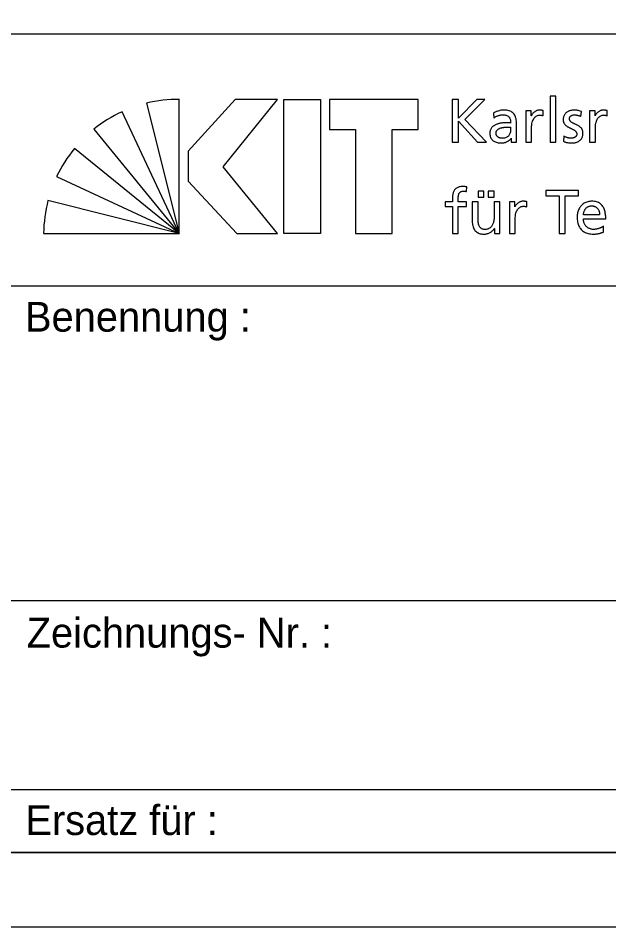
# Model space of a CAD drawing. Extents: x 0 to 29.7, y 0 to 21.
# Drawn here: x 25.283 to 27.266, y 0 to 3.052 of the extents above; entities that cross this region are included whole.
import ezdxf

# ---------------------------------------------------------------- set-up
doc = ezdxf.new("R2010")
doc.units = 0
doc.layers.add('90_Plankopf', color=7, linetype='Continuous')

msp = doc.modelspace()

# ---------------------------------------------------------------- linework, layer by layer
at = {"layer": '90_Plankopf'}
for p, q in [((20.556, 2.9995), (29.45, 2.9995)), ((20.556, 2.9995), (29.45, 2.9995)), ((25.824, 2.3293), (25.824, 2.7792)), ((26.7405, 2.7793), (26.7405, 2.6353)), ((25.7137, 2.7666), (25.824, 2.3293)), ((25.824, 2.3293), (25.6317, 2.7376)), ((26.879, 2.7331), (26.88, 2.7166)), ((27.0463, 2.7242), (27.0463, 2.7416)), ((27.1728, 2.722), (27.1745, 2.7389)), ((27.2606, 2.7242), (27.2606, 2.7416)), ((26.9559, 2.6559), (26.9559, 2.6995)), ((25.5372, 2.6793), (25.824, 2.3293)), ((26.9365, 2.6854), (26.9365, 2.6761)), ((27.1149, 2.6559), (27.1138, 2.6386)), ((26.7405, 2.6353), (26.7611, 2.6353)), ((26.8253, 2.6353), (26.8554, 2.6353)), ((25.824, 2.3293), (25.4717, 2.6143)), ((25.412, 2.5207), (25.824, 2.3293)), ((26.7887, 2.4696), (26.7895, 2.4853)), ((25.824, 2.3293), (25.3829, 2.4394)), ((26.9913, 2.4182), (26.9913, 2.4356)), ((27.2353, 2.392), (27.1808, 2.392)), ((27.1808, 2.3776), (27.2559, 2.3776)), ((27.2479, 2.3337), (27.2479, 2.353)), ((25.3682, 2.3293), (25.824, 2.3293)), ((25.2501, 2.1535), (29.45, 2.1535)), ((25.2501, 1.096), (29.45, 1.096)), ((25.2501, 0.4615), (29.45, 0.4615)), ((29.45, 0.25), (20.556, 0.25)), ((21.14, 0.25), (29.45, 0.25)), ((21.14, 0.25), (29.45, 0.25))]:
    msp.add_line(p, q, dxfattribs=at)
for points in [[(0, 0), (29.7, 0), (29.7, 21), (0, 21)], [(1.25, 20.75), (29.45, 20.75), (29.45, 0.25), (1.25, 0.25)], [(26.1533, 2.7793), (26.0118, 2.7793), (25.8536, 2.6049), (25.8536, 2.5046), (26.0169, 2.3293), (26.1542, 2.3293), (25.9711, 2.5531)], [(26.2985, 2.7793), (26.2985, 2.3293), (26.1751, 2.3293), (26.1751, 2.7793)], [(26.3281, 2.7793), (26.3281, 2.678), (26.4151, 2.678), (26.4151, 2.3293), (26.5385, 2.3293), (26.5385, 2.678), (26.6255, 2.678), (26.6255, 2.7793)]]:
    msp.add_lwpolyline(points, close=True, dxfattribs=at)
for points in [[(26.8554, 2.6353), (26.7824, 2.7112), (26.85, 2.7793), (26.8226, 2.7793), (26.7611, 2.716), (26.7611, 2.7793), (26.7405, 2.7793)], [(27.069, 2.6353), (27.0884, 2.6353), (27.0884, 2.79), (27.069, 2.79), (27.069, 2.6353)], [(27.0061, 2.7242), (27.0057, 2.7242), (27.0057, 2.7405), (26.9875, 2.7405), (26.9875, 2.6353), (27.0069, 2.6353), (27.0069, 2.6832)], [(27.2203, 2.7242), (27.2199, 2.7242), (27.2199, 2.7405), (27.2018, 2.7405), (27.2018, 2.6353), (27.2212, 2.6353), (27.2212, 2.6832)], [(26.7611, 2.6353), (26.7611, 2.7059), (26.8253, 2.6353)], [(26.9382, 2.6489), (26.9386, 2.6489), (26.9386, 2.6353), (26.9567, 2.6353)], [(27.0995, 2.3293), (27.1201, 2.3293), (27.1201, 2.4552), (27.1649, 2.4552), (27.1649, 2.4733), (27.0547, 2.4733), (27.0547, 2.4552), (27.0995, 2.4552), (27.0995, 2.3293)], [(26.7412, 2.4443), (26.7412, 2.4346), (26.7165, 2.4346), (26.7165, 2.4189), (26.7412, 2.4189), (26.7412, 2.3293), (26.7606, 2.3293), (26.7606, 2.4189), (26.7885, 2.4189), (26.7885, 2.4346), (26.7606, 2.4346), (26.7606, 2.4459)], [(26.8277, 2.4713), (26.8277, 2.4506), (26.8471, 2.4506), (26.8471, 2.4713), (26.8277, 2.4713)], [(26.8615, 2.4713), (26.8615, 2.4506), (26.8809, 2.4506), (26.8809, 2.4713), (26.8615, 2.4713)], [(26.8271, 2.3801), (26.8271, 2.4346), (26.8077, 2.4346), (26.8077, 2.372)], [(26.9007, 2.3293), (26.9007, 2.4346), (26.8813, 2.4346), (26.8813, 2.3859)], [(26.9511, 2.4182), (26.9507, 2.4182), (26.9507, 2.4346), (26.9325, 2.4346), (26.9325, 2.3293), (26.9519, 2.3293), (26.9519, 2.3772)], [(26.8816, 2.346), (26.882, 2.346), (26.882, 2.3293), (26.9007, 2.3293)]]:
    msp.add_lwpolyline(points, dxfattribs=at)
for centre, start, end in [((25.8224, 2.3028), 89.8053, 103.1895), ((25.8331, 2.3059), 115.0126, 128.3968), ((25.8408, 2.3131), 140.7898, 154.174), ((25.8446, 2.3219), 165.7222, 179.1064)]:
    msp.add_arc(centre, 0.4764, start, end, dxfattribs=at)
for points in [[(26.9559, 2.6995), (26.956, 2.709), (26.9545, 2.717), (26.9517, 2.7235), (26.9488, 2.73), (26.9442, 2.7348), (26.938, 2.7381), (26.9317, 2.7413), (26.9236, 2.743), (26.9136, 2.743), (26.9069, 2.743), (26.9007, 2.742), (26.8949, 2.7402), (26.8891, 2.7384), (26.8838, 2.7361), (26.879, 2.7331)], [(26.88, 2.7166), (26.8826, 2.7188), (26.8856, 2.7207), (26.889, 2.7223), (26.8923, 2.7239), (26.8958, 2.7251), (26.8995, 2.726), (26.9032, 2.7269), (26.9068, 2.7273), (26.9105, 2.7273), (26.917, 2.7273), (26.9221, 2.7263), (26.9259, 2.7243), (26.9297, 2.7222), (26.9324, 2.7191), (26.9341, 2.7151), (26.9358, 2.711), (26.9365, 2.7059), (26.9365, 2.6999)], [(27.0463, 2.7416), (27.045, 2.7418), (27.0437, 2.7421), (27.0425, 2.7423), (27.0412, 2.7425), (27.0399, 2.7427), (27.0385, 2.7428), (27.0371, 2.7429), (27.0354, 2.743), (27.0335, 2.743), (27.0298, 2.743), (27.0261, 2.7422), (27.0226, 2.7406), (27.0191, 2.739), (27.0159, 2.7368), (27.013, 2.7339), (27.0101, 2.7311), (27.0078, 2.7279), (27.0061, 2.7242)], [(27.0069, 2.6832), (27.0069, 2.692), (27.0081, 2.6996), (27.0105, 2.706), (27.0129, 2.7124), (27.0162, 2.7174), (27.0205, 2.7208), (27.0247, 2.7243), (27.0298, 2.726), (27.0356, 2.7261), (27.0373, 2.7261), (27.039, 2.726), (27.0409, 2.7257), (27.0427, 2.7254), (27.0445, 2.7249), (27.0463, 2.7242)], [(27.1745, 2.7389), (27.1707, 2.74), (27.1669, 2.741), (27.163, 2.7418), (27.1591, 2.7426), (27.1549, 2.743), (27.1504, 2.743), (27.1451, 2.743), (27.1403, 2.7423), (27.1358, 2.741), (27.1313, 2.7397), (27.1274, 2.7377), (27.124, 2.735), (27.1206, 2.7323), (27.118, 2.729), (27.1161, 2.7249), (27.1142, 2.7208), (27.1132, 2.7161), (27.1132, 2.7106), (27.1132, 2.7064), (27.1141, 2.7028), (27.1158, 2.6997), (27.1174, 2.6966), (27.1195, 2.694), (27.1223, 2.6917), (27.125, 2.6895), (27.1279, 2.6875), (27.1312, 2.6857), (27.1344, 2.684), (27.1376, 2.6824), (27.1409, 2.6809), (27.1441, 2.6793), (27.1471, 2.6777), (27.1498, 2.6761), (27.1525, 2.6745), (27.1547, 2.6727), (27.1563, 2.6706), (27.1579, 2.6686), (27.1588, 2.6663), (27.1588, 2.6636), (27.1588, 2.6607), (27.1582, 2.6584), (27.157, 2.6564), (27.1558, 2.6545), (27.1542, 2.6529), (27.1522, 2.6518), (27.1503, 2.6506), (27.1482, 2.6498), (27.1459, 2.6493), (27.1435, 2.6487), (27.1412, 2.6485), (27.139, 2.6485), (27.1371, 2.6485), (27.1347, 2.6488), (27.132, 2.6493), (27.1292, 2.6499), (27.1263, 2.6507), (27.1233, 2.6518), (27.1203, 2.6529), (27.1175, 2.6543), (27.1149, 2.6559)], [(27.1138, 2.6386), (27.1183, 2.6363), (27.123, 2.6347), (27.1279, 2.6339), (27.1328, 2.6331), (27.1377, 2.6327), (27.1427, 2.6328), (27.1475, 2.6328), (27.152, 2.6335), (27.1564, 2.6348), (27.1607, 2.6361), (27.1647, 2.6381), (27.1681, 2.6408), (27.1716, 2.6435), (27.1743, 2.6469), (27.1764, 2.651), (27.1784, 2.6551), (27.1794, 2.66), (27.1795, 2.6656), (27.1794, 2.6704), (27.1786, 2.6745), (27.1769, 2.6778), (27.1753, 2.6811), (27.1731, 2.684), (27.1704, 2.6863), (27.1677, 2.6886), (27.1647, 2.6906), (27.1615, 2.6922), (27.1583, 2.6939), (27.155, 2.6954), (27.1518, 2.6968), (27.1486, 2.6983), (27.1456, 2.6998), (27.1429, 2.7013), (27.1402, 2.7029), (27.138, 2.7047), (27.1364, 2.7068), (27.1347, 2.7089), (27.1339, 2.7115), (27.1338, 2.7145), (27.1339, 2.7174), (27.1348, 2.7198), (27.1365, 2.7217), (27.1382, 2.7236), (27.1404, 2.725), (27.1432, 2.7259), (27.146, 2.7269), (27.1491, 2.7273), (27.1524, 2.7273), (27.1536, 2.7273), (27.1551, 2.7271), (27.1569, 2.7269), (27.1588, 2.7266), (27.1607, 2.7261), (27.1627, 2.7256), (27.1648, 2.7251), (27.1667, 2.7246), (27.1685, 2.7239), (27.1703, 2.7233), (27.1717, 2.7226), (27.1728, 2.722)], [(27.2606, 2.7416), (27.2592, 2.7418), (27.2579, 2.7421), (27.2567, 2.7423), (27.2555, 2.7425), (27.2541, 2.7427), (27.2527, 2.7428), (27.2513, 2.7429), (27.2497, 2.743), (27.2478, 2.743), (27.244, 2.743), (27.2404, 2.7422), (27.2368, 2.7406), (27.2333, 2.739), (27.2301, 2.7368), (27.2273, 2.7339), (27.2244, 2.7311), (27.2221, 2.7279), (27.2203, 2.7242)], [(27.2212, 2.6832), (27.2212, 2.692), (27.2224, 2.6996), (27.2247, 2.706), (27.2271, 2.7124), (27.2304, 2.7174), (27.2347, 2.7208), (27.239, 2.7243), (27.244, 2.726), (27.2498, 2.7261), (27.2515, 2.7261), (27.2533, 2.726), (27.2551, 2.7257), (27.257, 2.7254), (27.2588, 2.7249), (27.2606, 2.7242)], [(26.9365, 2.6999), (26.934, 2.7), (26.9317, 2.7001), (26.9295, 2.7001), (26.9273, 2.7002), (26.9251, 2.7003), (26.9229, 2.7003), (26.9208, 2.7003), (26.9184, 2.7003), (26.9159, 2.7003), (26.9118, 2.7003), (26.9076, 2.6999), (26.9031, 2.6992), (26.8987, 2.6985), (26.8943, 2.6973), (26.89, 2.6957), (26.8858, 2.6941), (26.8819, 2.6919), (26.8784, 2.6892), (26.875, 2.6866), (26.8722, 2.6833), (26.8701, 2.6794), (26.8681, 2.6755), (26.8671, 2.6709), (26.867, 2.6656), (26.8671, 2.658), (26.8687, 2.6518), (26.8719, 2.6469), (26.8752, 2.6421), (26.8797, 2.6385), (26.8855, 2.6362), (26.8913, 2.6339), (26.8979, 2.6328), (26.9056, 2.6328), (26.91, 2.6328), (26.914, 2.6334), (26.9175, 2.6344), (26.921, 2.6355), (26.9241, 2.6368), (26.9268, 2.6384), (26.9295, 2.6401), (26.9318, 2.6419), (26.9337, 2.6437), (26.9355, 2.6455), (26.937, 2.6472), (26.9382, 2.6489)], [(26.9365, 2.6761), (26.9365, 2.6709), (26.9354, 2.6661), (26.9332, 2.662), (26.931, 2.6578), (26.9277, 2.6546), (26.9233, 2.6522), (26.919, 2.6498), (26.9136, 2.6485), (26.9072, 2.6485), (26.905, 2.6485), (26.9027, 2.6489), (26.9004, 2.6496), (26.8981, 2.6503), (26.896, 2.6514), (26.8941, 2.6529), (26.8922, 2.6543), (26.8906, 2.6561), (26.8894, 2.6582), (26.8883, 2.6604), (26.8877, 2.6628), (26.8876, 2.6656), (26.8877, 2.6693), (26.8886, 2.6724), (26.8904, 2.6749), (26.8922, 2.6773), (26.8946, 2.6793), (26.8975, 2.6807), (26.9003, 2.6822), (26.9034, 2.6833), (26.9067, 2.6841), (26.91, 2.6848), (26.9132, 2.6853), (26.9163, 2.6855), (26.9194, 2.6858), (26.922, 2.6859), (26.9241, 2.6858), (26.9262, 2.6858), (26.9283, 2.6858), (26.9303, 2.6856), (26.9324, 2.6855), (26.9345, 2.6855), (26.9365, 2.6854)], [(26.9567, 2.6353), (26.9566, 2.6363), (26.9565, 2.6377), (26.9563, 2.6393), (26.9562, 2.6411), (26.9561, 2.6433), (26.9561, 2.646), (26.956, 2.6486), (26.9559, 2.652), (26.9559, 2.6559)], [(26.7895, 2.4853), (26.7875, 2.4856), (26.7855, 2.4859), (26.7834, 2.4862), (26.7812, 2.4864), (26.779, 2.4866), (26.7765, 2.4866), (26.7694, 2.4865), (26.7635, 2.4855), (26.7589, 2.4836), (26.7543, 2.4816), (26.7507, 2.4787), (26.7481, 2.475), (26.7455, 2.4713), (26.7437, 2.4668), (26.7427, 2.4616), (26.7417, 2.4565), (26.7412, 2.4507), (26.7412, 2.4443)], [(26.7606, 2.4459), (26.7606, 2.4495), (26.7608, 2.4528), (26.7612, 2.4558), (26.7616, 2.4588), (26.7625, 2.4615), (26.7637, 2.4637), (26.765, 2.466), (26.7669, 2.4677), (26.7694, 2.469), (26.7719, 2.4702), (26.7752, 2.4709), (26.7794, 2.4709), (26.7811, 2.4709), (26.7828, 2.4708), (26.7844, 2.4706), (26.7861, 2.4703), (26.7875, 2.47), (26.7887, 2.4696)], [(26.9913, 2.4356), (26.99, 2.4359), (26.9887, 2.4361), (26.9875, 2.4363), (26.9863, 2.4365), (26.9849, 2.4367), (26.9835, 2.4368), (26.9821, 2.437), (26.9804, 2.437), (26.9786, 2.437), (26.9748, 2.437), (26.9712, 2.4362), (26.9676, 2.4346), (26.9641, 2.433), (26.9609, 2.4308), (26.9581, 2.428), (26.9552, 2.4252), (26.9529, 2.4219), (26.9511, 2.4182)], [(26.9519, 2.3772), (26.952, 2.386), (26.9532, 2.3937), (26.9555, 2.4001), (26.9579, 2.4065), (26.9612, 2.4114), (26.9655, 2.4148), (26.9698, 2.4183), (26.9748, 2.4201), (26.9806, 2.4201), (26.9823, 2.4201), (26.9841, 2.42), (26.9859, 2.4197), (26.9878, 2.4195), (26.9896, 2.419), (26.9913, 2.4182)], [(27.2559, 2.3776), (27.256, 2.3861), (27.2552, 2.394), (27.2536, 2.4012), (27.252, 2.4084), (27.2495, 2.4146), (27.2459, 2.42), (27.2423, 2.4254), (27.2375, 2.4295), (27.2315, 2.4325), (27.2256, 2.4355), (27.2182, 2.437), (27.2095, 2.437), (27.202, 2.437), (27.1953, 2.4357), (27.1892, 2.4331), (27.1832, 2.4305), (27.178, 2.4269), (27.1737, 2.4221), (27.1694, 2.4174), (27.166, 2.4118), (27.1637, 2.4052), (27.1614, 2.3988), (27.1602, 2.3916), (27.1602, 2.3838), (27.1602, 2.3752), (27.1613, 2.3674), (27.1634, 2.3604), (27.1656, 2.3535), (27.169, 2.3475), (27.1734, 2.3425), (27.1779, 2.3375), (27.1835, 2.3336), (27.1904, 2.3309), (27.1973, 2.3282), (27.2053, 2.3269), (27.2147, 2.3268), (27.2204, 2.3269), (27.2253, 2.3273), (27.2293, 2.328), (27.2334, 2.3288), (27.2369, 2.3297), (27.2398, 2.3307), (27.2428, 2.3317), (27.2454, 2.3327), (27.2479, 2.3337)], [(27.1808, 2.392), (27.1812, 2.3955), (27.182, 2.3989), (27.1832, 2.4024), (27.1844, 2.4058), (27.1861, 2.4089), (27.1884, 2.4118), (27.1906, 2.4147), (27.1934, 2.417), (27.1969, 2.4187), (27.2003, 2.4204), (27.2043, 2.4213), (27.2091, 2.4213), (27.2133, 2.4213), (27.217, 2.4206), (27.2202, 2.419), (27.2235, 2.4175), (27.2262, 2.4154), (27.2285, 2.4127), (27.2307, 2.4101), (27.2324, 2.4069), (27.2335, 2.4034), (27.2347, 2.3999), (27.2353, 2.3961), (27.2353, 2.392)], [(26.8813, 2.3859), (26.8813, 2.3794), (26.8807, 2.3736), (26.8795, 2.3683), (26.8782, 2.363), (26.8763, 2.3584), (26.8736, 2.3546), (26.871, 2.3507), (26.8677, 2.3478), (26.8637, 2.3457), (26.8596, 2.3436), (26.8549, 2.3426), (26.8494, 2.3425), (26.8438, 2.3429), (26.8393, 2.3444), (26.8361, 2.3473), (26.8328, 2.3501), (26.8305, 2.3542), (26.8291, 2.3597), (26.8277, 2.3651), (26.8271, 2.3719), (26.8271, 2.3801)], [(26.8077, 2.372), (26.8077, 2.3626), (26.8091, 2.3545), (26.8118, 2.3478), (26.8146, 2.341), (26.819, 2.3359), (26.8248, 2.3323), (26.8306, 2.3287), (26.838, 2.3269), (26.8471, 2.3268), (26.852, 2.3269), (26.8568, 2.3276), (26.8613, 2.3291), (26.8658, 2.3307), (26.8698, 2.3329), (26.8733, 2.3357), (26.8768, 2.3386), (26.8796, 2.342), (26.8816, 2.346)], [(27.2479, 2.353), (27.2467, 2.3521), (27.2449, 2.351), (27.2426, 2.3497), (27.2403, 2.3485), (27.2377, 2.3474), (27.2347, 2.3463), (27.2317, 2.3452), (27.2286, 2.3443), (27.2253, 2.3436), (27.222, 2.3429), (27.2187, 2.3426), (27.2155, 2.3425), (27.2108, 2.3426), (27.2065, 2.3434), (27.2023, 2.3451), (27.1982, 2.3468), (27.1945, 2.3492), (27.1913, 2.3523), (27.188, 2.3554), (27.1855, 2.359), (27.1836, 2.3633), (27.1818, 2.3676), (27.1809, 2.3724), (27.1808, 2.3776)]]:
    msp.add_open_spline(points, degree=3, dxfattribs=at)

# ---------------------------------------------------------------- texts
for s, p in [('Benennung :', (25.3057, 1.999)), ('Zeichnungs- Nr. :', (25.3114, 0.9379)), ('Ersatz für :', (25.3069, 0.3084))]:
    msp.add_text(s, height=0.1, dxfattribs=at).set_placement(p)

doc.saveas('drawing.dxf')
